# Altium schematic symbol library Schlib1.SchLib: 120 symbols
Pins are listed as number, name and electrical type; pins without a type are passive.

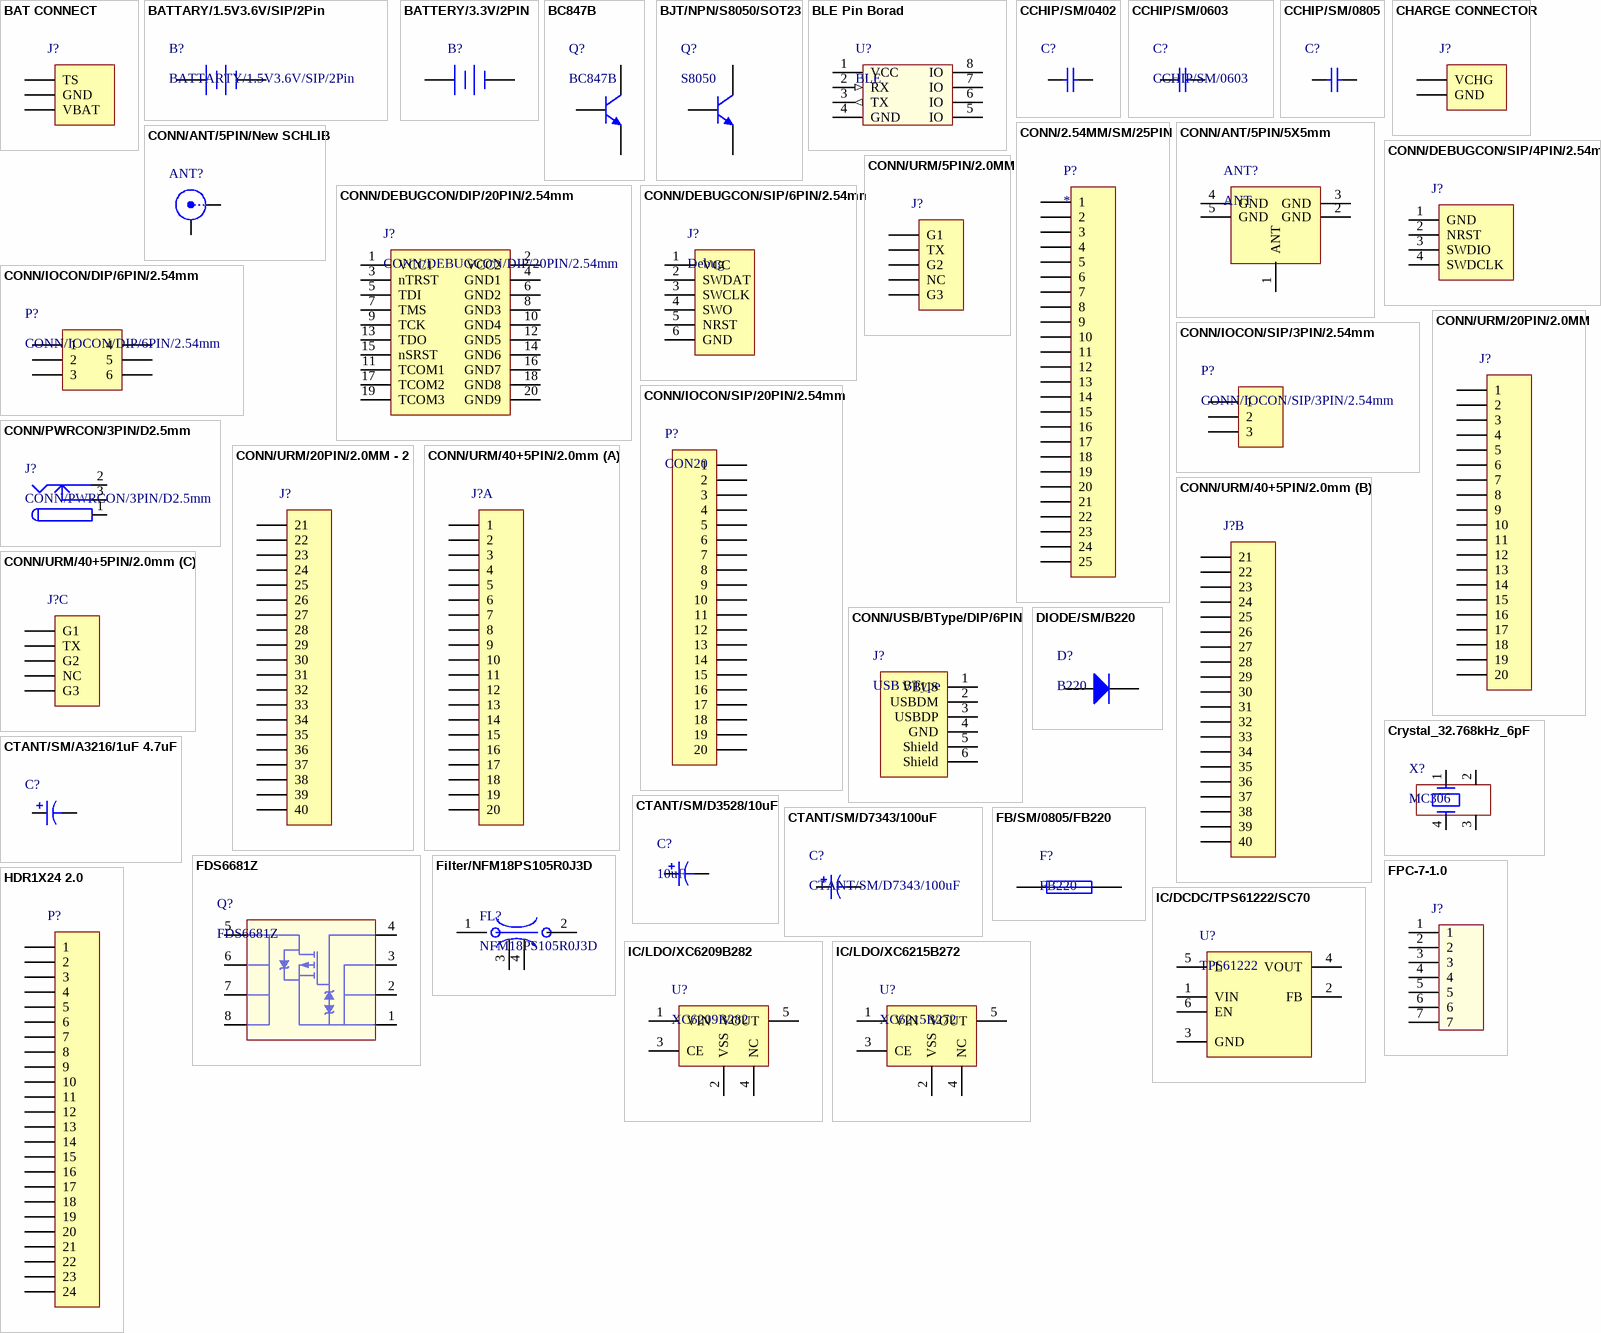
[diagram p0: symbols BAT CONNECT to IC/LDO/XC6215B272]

## BAT CONNECT
designator J?, comment XH-3  (value not drawn)
XH-3 2.0MM 3PIN
footprint XH-3
pins: 1 TS, 2 GND, 3 VBAT

## BATTARY/1.5V3.6V/SIP/2Pin
designator B?, comment BATTARTY/1.5V3.6V/SIP/2Pin
1.5V/3.6V AA电池座(5号电池)
footprint CONN/BATBOX/1.5V/14500
pins: 1 +, 2 -

## BATTERY/3.3V/2PIN
designator B?  (value not drawn)
3.3V纽扣电池(4节并联)CR2032
footprint BATTERY/3.3V/2PIN
pins: 1 +, 2 -

## BC847B
designator Q?
General purpose NPN Transistor
footprint SOT23_BC847B
pins: 1 B, 2 E, 3 C

## BJT/NPN/S8050/SOT23
designator Q?, comment S8050
NPN小功率三极管
footprint SOT-23-3
pins: 1 B, 2 E, 3 C

## BLE Pin Borad
designator U?, comment BLE
BLE Pin Board USRAT SPI  I2C
footprint BLE Pin Board
pins: 1 VCC (power), 2 RX (in), 3 TX (out), 4 GND (power), 5 IO, 6 IO, 7 IO, 8 IO

## CCHIP/SM/0402
designator C?  (value not drawn)
0402贴片电容
footprint 0402 with no topoverlayer
pins: 1, 2

## CCHIP/SM/0603
designator C?
瓷片电容
footprint 0603c
footprint 0402
footprint 0805C
footprint 0603 with no topoverlay
pins: 1, 2

## CCHIP/SM/0805
designator C?  (value not drawn)
瓷片电容
footprint 0805 with no topoverlay
pins: 1, 2

## CHARGE CONNECTOR
designator J?  (value not drawn)
Charge Connector XH-2 2.0MM
footprint XH-2
pins: 1 VCHG, 2 GND

## CONN/2.54MM/SM/25PIN
designator P?
2.54mm间距 25pin 贴片排针
footprint CONN/25PIN/2.54MM/SM
pins: 1, 2, 3, 4, 5, 6, 7, 8, 9, 10, 11, 12, 13, 14, 15, 16, 17, 18, 19, 20, 21, 22, 23, 24, 25

## CONN/ANT/5PIN/5X5mm
designator ANT?, comment ANT
直插天线接口,5PIN,5X5mm
footprint CONN/ANT/5PIN/5X5mm
pins: 1 ANT, 2 GND, 3 GND, 4 GND, 5 GND

## CONN/ANT/5PIN/New SCHLIB
designator ANT?  (value not drawn)
天线连接器
pins: 1 Signal "RF signal", 2 GND "Ground signal", 3 hidden to GND, 4 hidden to GND, 5 hidden to GND

## CONN/DEBUGCON/DIP/20PIN/2.54mm
designator J?
STM32调试接口双排20pin
footprint CONN/DEBUGCON/20PIN
pins: 1 VCC1, 2 VCC2, 3 nTRST, 4 GND1, 5 TDI, 6 GND2, 7 TMS, 8 GND3, 9 TCK, 10 GND4, 11 TCOM1, 12 GND5, 13 TDO, 14 GND6, 15 nSRST, 16 GND7, 17 TCOM2, 18 GND8, 19 TCOM3, 20 GND9

## CONN/DEBUGCON/SIP/4PIN/2.54mm
designator J?  (value not drawn)
STM32仿真、下载接口，4pin，2.54mm
footprint CONN/DEBUGCON/4PIN/2.54MM
footprint CONN/DEBUG CON/2.54mm/4pin/SMT
footprint CONN/FPC/4PIN/0.5MM
pins: 1 GND, 2 NRST, 3 SWDIO, 4 SWDCLK

## CONN/DEBUGCON/SIP/6PIN/2.54mm
designator J?, comment Debug
STM32仿真、下载接口，6pin，2.54mm
footprint CONN/DEBUGCON/SIP/6PIN/2.54mm
pins: 1 VCC, 2 SWDAT, 3 SWCLK, 4 SWO, 5 NRST, 6 GND

## CONN/IOCON/DIP/6PIN/2.54mm
designator P?
2.54mm双排直插6PIN插针
pins: 1, 2, 3, 4, 5, 6

## CONN/IOCON/SIP/3PIN/2.54mm
designator P?
2.54mm单排3pin插针
footprint CONN/SIP/3PIN/2.54mm
pins: 1, 2, 3

## CONN/IOCON/SIP/20PIN/2.54mm
designator P?, comment CON20
20PIN，2.54mm间距接插件
footprint CONN/IOCON/SIP/20PIN/2.54mm
pins: 1, 2, 3, 4, 5, 6, 7, 8, 9, 10, 11, 12, 13, 14, 15, 16, 17, 18, 19, 20

## CONN/PWRCON/3PIN/D2.5mm
designator J?
2.5mm直径电源接头
pins: 1 (power), 1A (power), 1B (power), 2 (power), 2A (power), 2B (power), 3 (power), 3A (power), 3B (power)

## CONN/URM/5PIN/2.0MM
designator J?  (value not drawn)
URM模块引脚,5PIN,2.0MM
footprint CONN/URM/5PIN/2.0MM
pins: G1, G2, G3, NC, TX

## CONN/URM/20PIN/2.0MM
designator J?  (value not drawn)
URM模块引脚,20PIN,2.0MM
footprint CON/URM/20PIN/2.0MM
pins: 1, 2, 3, 4, 5, 6, 7, 8, 9, 10, 11, 12, 13, 14, 15, 16, 17, 18, 19, 20

## CONN/URM/20PIN/2.0MM - 2
designator J?  (value not drawn)
URM模块引脚,20PIN,2.0MM - 2
footprint CONN/URM/20PIN/2.0MM - 2
pins: 21, 22, 23, 24, 25, 26, 27, 28, 29, 30, 31, 32, 33, 34, 35, 36, 37, 38, 39, 40

## CONN/URM/40+5PIN/2.0mm
designator J?  (value not drawn)
URM模块引脚,带边框
footprint URM CONN with Outline
part A pins: 1, 2, 3, 4, 5, 6, 7, 8, 9, 10, 11, 12, 13, 14, 15, 16, 17, 18, 19, 20
part B pins: 21, 22, 23, 24, 25, 26, 27, 28, 29, 30, 31, 32, 33, 34, 35, 36, 37, 38, 39, 40
part C pins: G1, G2, G3, NC, TX

## CONN/USB/BType/DIP/6PIN
designator J?, comment USB BType
B型USB母头方口
footprint CONN/USB/BType/DIP/6PIN
pins: 1 VBUS, 2 USBDM, 3 USBDP, 4 GND, 5 Shield, 6 Shield

## Crystal_32.768kHz_6pF
designator X?, comment MC306
EPSON 32.768kHz 6pF 20ppm
footprint SM8
pins: 1, 2, 3, 4

## CTANT/SM/A3216/1uF 4.7uF
designator C?  (value not drawn)
A3216型钽电容1uF 16V或4.7uF 10V
footprint A3216
pins: 1, 2

## CTANT/SM/D3528/10uF
designator C?, comment 10uF
D3528贴片钽电容10uF
footprint D3528
pins: 1, 2

## CTANT/SM/D7343/100uF
designator C?
D7343 钽电容
footprint D7343
pins: 1, 2

## DIODE/SM/B220
designator D?, comment B220
B220贴片二极管
footprint DIODE/SM/B220
pins: 1 A, 2 K

## FB/SM/0805/FB220
designator F?, comment FB220
磁珠
footprint 0805C
footprint 2012-L
pins: 1, 2

## FDS6681Z
designator Q?
P Channel MOS Vgs = -4.5V Rds = 6.5mΩ
footprint SO-8
pins: 1 S, 2 S, 3 S, 4 G, 5 D, 6 D, 7 D, 8 D

## Filter/NFM18PS105R0J3D
designator FL?, comment NFM18PS105R0J3D
SURFACE MOUNT EMI FILTERS/MURATA
footprint Filter/Surface Mount EMI Filters
pins: 1, 2, 3, 4

## FPC-7-1.0
designator J?  (value not drawn)
FPC 7pin 1.0mm
footprint FPC-7-1.0
pins: 1, 2, 3, 4, 5, 6, 7

## HDR1X24 2.0
designator P?  (value not drawn)
CONNECTOR 1X24Pin 2.0mm
footprint HDR1X24 2.0mm
pins: 1, 2, 3, 4, 5, 6, 7, 8, 9, 10, 11, 12, 13, 14, 15, 16, 17, 18, 19, 20, 21, 22, 23, 24

## IC/DCDC/TPS61222/SC70
designator U?, comment TPS61222
升压电源IC 0.7 - 5V转5V
footprint SC70
pins: 1 VIN, 2 FB, 3 GND, 4 VOUT, 5 L, 6 EN

## IC/LDO/XC6209B282
designator U?, comment XC6209B282
2.8V 150mA 25uA-Iq LDO
footprint SOT-25
pins: 1 VIN, 2 VSS, 3 CE, 4 NC, 5 VOUT

## IC/LDO/XC6215B272
designator U?, comment XC6215B272
2.7V 150mA 0.8uA-Iq LDO
footprint SOT-25
pins: 1 VIN, 2 VSS, 3 CE, 4 NC, 5 VOUT

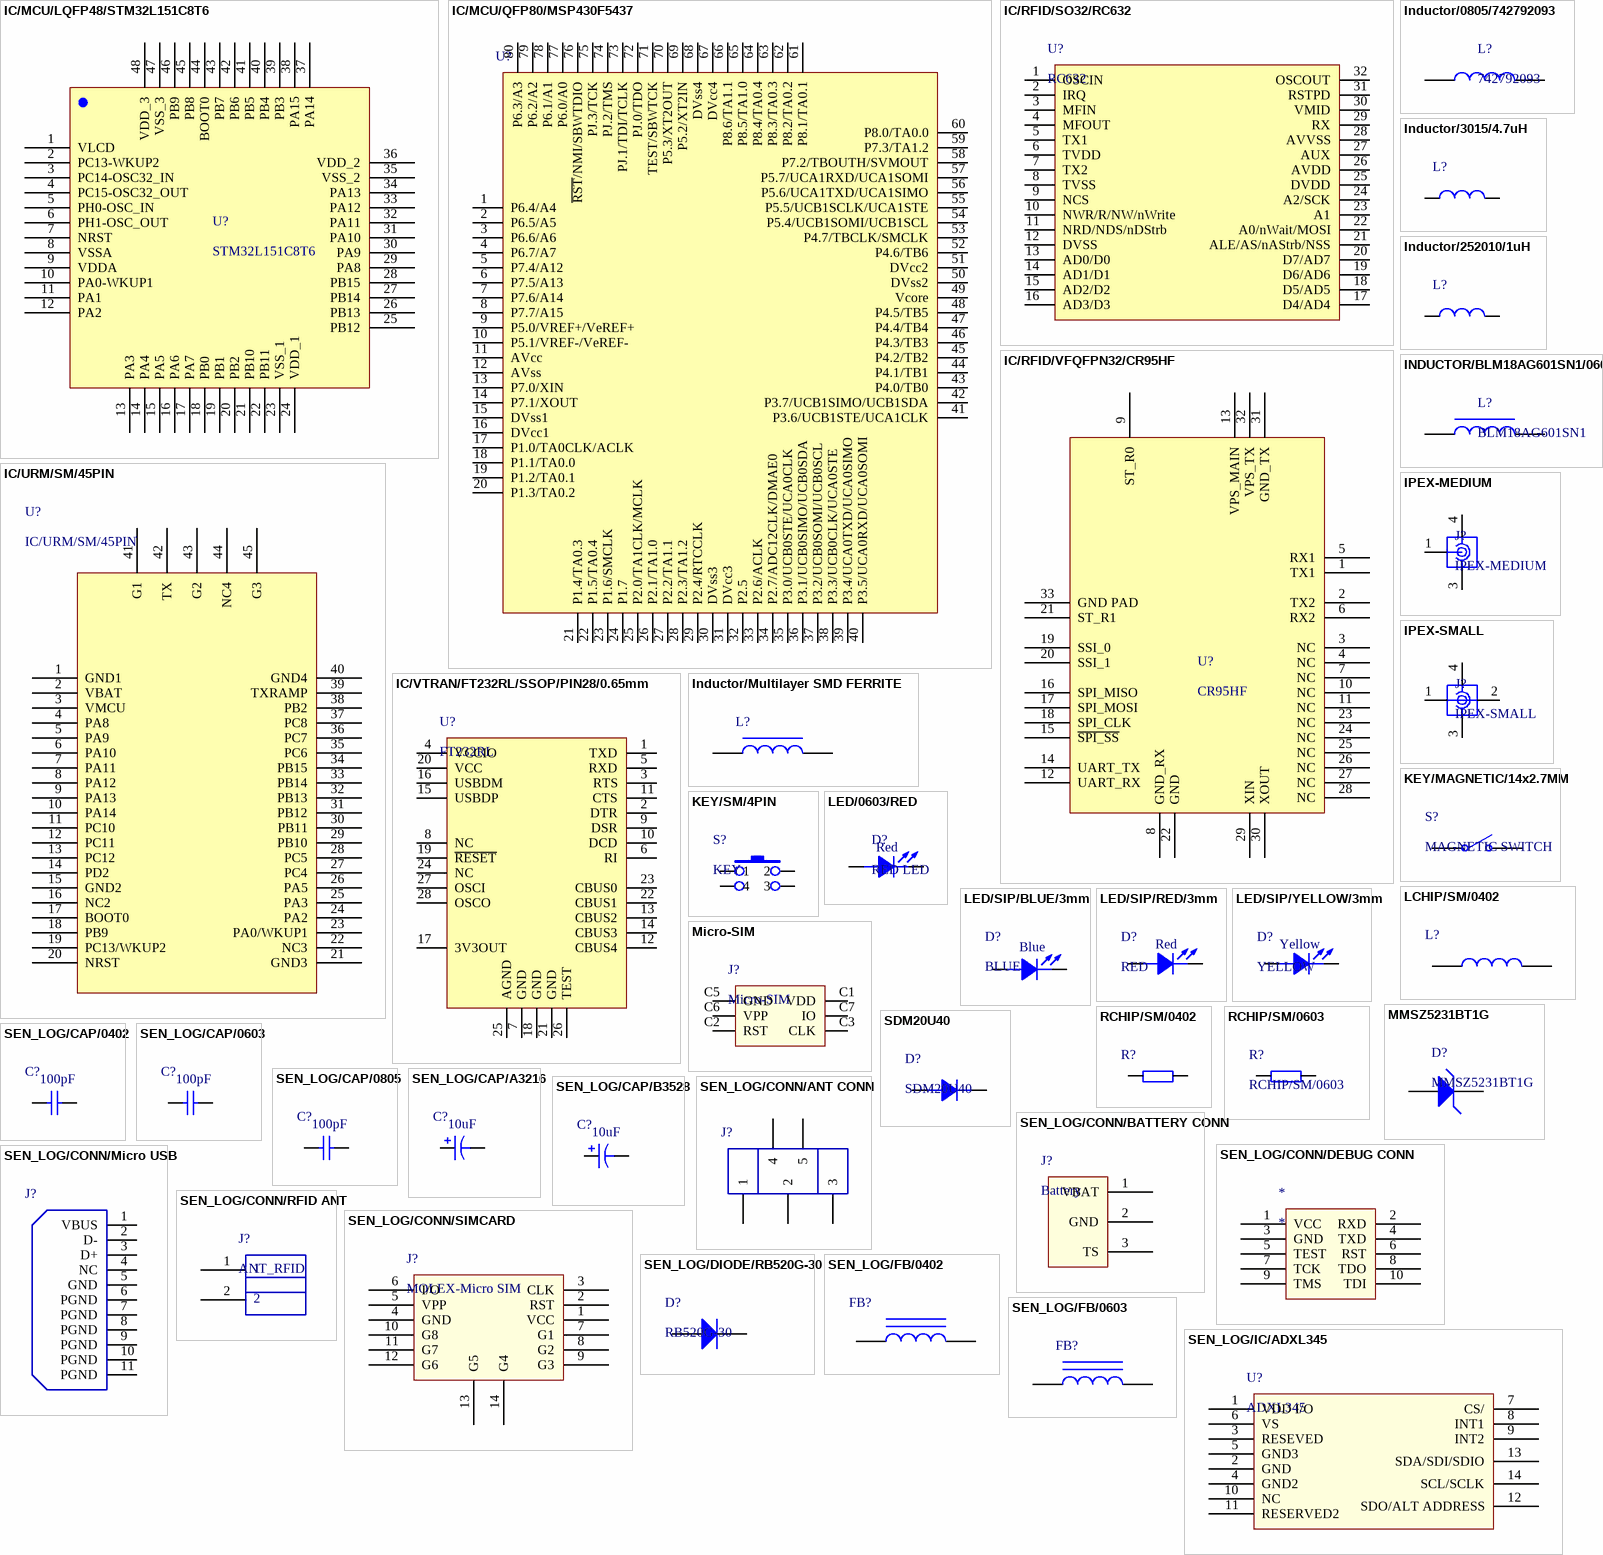
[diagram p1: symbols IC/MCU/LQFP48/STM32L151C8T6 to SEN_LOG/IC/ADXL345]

## IC/MCU/LQFP48/STM32L151C8T6
designator U?, comment STM32L151C8T6
ARM M3 内核低功耗处理器
footprint LQFP48
pins: 1 VLCD, 2 PC13-WKUP2, 3 PC14-OSC32_IN, 4 PC15-OSC32_OUT, 5 PH0-OSC_IN, 6 PH1-OSC_OUT, 7 NRST, 8 VSSA, 9 VDDA, 10 PA0-WKUP1, 11 PA1, 12 PA2, 13 PA3, 14 PA4, 15 PA5, 16 PA6, 17 PA7, 18 PB0, 19 PB1, 20 PB2, 21 PB10, 22 PB11, 23 VSS_1, 24 VDD_1, 25 PB12, 26 PB13, 27 PB14, 28 PB15, 29 PA8, 30 PA9, 31 PA10, 32 PA11, 33 PA12, 34 PA13, 35 VSS_2, 36 VDD_2, 37 PA14, 38 PA15, 39 PB3, 40 PB4, 41 PB5, 42 PB6, 43 PB7, 44 BOOT0, 45 PB8, 46 PB9, 47 VSS_3, 48 VDD_3

## IC/MCU/QFP80/MSP430F5437
designator U?  (value not drawn)
16位低功耗单片机
footprint QFP80/MSP430F5437
pins: 1 P6.4/A4, 2 P6.5/A5, 3 P6.6/A6, 4 P6.7/A7, 5 P7.4/A12, 6 P7.5/A13, 7 P7.6/A14, 8 P7.7/A15, 9 P5.0/VREF+/VeREF+, 10 P5.1/VREF-/VeREF-, 11 AVcc, 12 AVss, 13 P7.0/XIN, 14 P7.1/XOUT, 15 DVss1, 16 DVcc1, 17 P1.0/TA0CLK/ACLK, 18 P1.1/TA0.0, 19 P1.2/TA0.1, 20 P1.3/TA0.2, 21 P1.4/TA0.3, 22 P1.5/TA0.4, 23 P1.6/SMCLK, 24 P1.7, 25 P2.0/TA1CLK/MCLK, 26 P2.1/TA1.0, 27 P2.2/TA1.1, 28 P2.3/TA1.2, 29 P2.4/RTCCLK, 30 DVss3, 31 DVcc3, 32 P2.5, 33 P2.6/ACLK, 34 P2.7/ADC12CLK/DMAE0, 35 P3.0/UCB0STE/UCA0CLK, 36 P3.1/UCB0SIMO/UCB0SDA, 37 P3.2/UCB0SOMI/UCB0SCL, 38 P3.3/UCB0CLK/UCA0STE, 39 P3.4/UCA0TXD/UCA0SIMO, 40 P3.5/UCA0RXD/UCA0SOMI, 41 P3.6/UCB1STE/UCA1CLK, 42 P3.7/UCB1SIMO/UCB1SDA, 43 P4.0/TB0, 44 P4.1/TB1, 45 P4.2/TB2, 46 P4.3/TB3, 47 P4.4/TB4, 48 P4.5/TB5, 49 Vcore, 50 DVss2, 51 DVcc2, 52 P4.6/TB6, 53 P4.7/TBCLK/SMCLK, 54 P5.4/UCB1SOMI/UCB1SCL, 55 P5.5/UCB1SCLK/UCA1STE, 56 P5.6/UCA1TXD/UCA1SIMO, 57 P5.7/UCA1RXD/UCA1SOMI, 58 P7.2/TBOUTH/SVMOUT, 59 P7.3/TA1.2, 60 P8.0/TA0.0, 61 P8.1/TA0.1, 62 P8.2/TA0.2, 63 P8.3/TA0.3, 64 P8.4/TA0.4, 65 P8.5/TA1.0, 66 P8.6/TA1.1, 67 DVcc4, 68 DVss4, 69 P5.2/XT2IN, 70 P5.3/XT2OUT, 71 TEST/SBWTCK, 72 PJ.0/TDO, 73 PJ.1/TDI/TCLK, 74 PJ.2/TMS, 75 PJ.3/TCK, 76 ~{RST}/NMI/SBWTDIO, 77 P6.0/A0, 78 P6.1/A1, 79 P6.2/A2, 80 P6.3/A3

## IC/RFID/SO32/RC632
designator U?, comment RC632
支持14443A、14443B、15693协议的RFID基站芯片
footprint SO32
pins: 1 OSCIN, 2 IRQ, 3 MFIN, 4 MFOUT, 5 TX1, 6 TVDD, 7 TX2, 8 TVSS, 9 NCS, 10 NWR/R/NW/nWrite, 11 NRD/NDS/nDStrb, 12 DVSS, 13 AD0/D0, 14 AD1/D1, 15 AD2/D2, 16 AD3/D3, 17 D4/AD4, 18 D5/AD5, 19 D6/AD6, 20 D7/AD7, 21 ALE/AS/nAStrb/NSS, 22 A0/nWait/MOSI, 23 A1, 24 A2/SCK, 25 DVDD, 26 AVDD, 27 AUX, 28 AVVSS, 29 RX, 30 VMID, 31 RSTPD, 32 OSCOUT

## IC/RFID/VFQFPN32/CR95HF
designator U?, comment CR95HF
RFID读写芯片，支持14443A、B及15693
footprint VFQFPN32 (CR95HF)
pins: 1 TX1, 2 TX2, 3 NC, 4 NC, 5 RX1, 6 RX2, 7 NC, 8 GND_RX, 9 ST_R0, 10 NC, 11 NC, 12 UART_RX, 13 VPS_MAIN, 14 UART_TX, 15 ~{SPI_SS}, 16 SPI_MISO, 17 SPI_MOSI, 18 SPI_CLK, 19 SSI_0, 20 SSI_1, 21 ST_R1, 22 GND, 23 NC, 24 NC, 25 NC, 26 NC, 27 NC, 28 NC, 29 XIN, 30 XOUT, 31 GND_TX, 32 VPS_TX, 33 GND PAD

## IC/URM/SM/45PIN
designator U?
URM模块
footprint IC/URM/45PIN
pins: 1 GND1, 2 VBAT, 3 VMCU, 4 PA8, 5 PA9, 6 PA10, 7 PA11, 8 PA12, 9 PA13, 10 PA14, 11 PC10, 12 PC11, 13 PC12, 14 PD2, 15 GND2, 16 NC2, 17 BOOT0, 18 PB9, 19 PC13/WKUP2, 20 NRST, 21 GND3, 22 NC3, 23 PA0/WKUP1, 24 PA2, 25 PA3, 26 PA5, 27 PC4, 28 PC5, 29 PB10, 30 PB11, 31 PB12, 32 PB13, 33 PB14, 34 PB15, 35 PC6, 36 PC7, 37 PC8, 38 PB2, 39 TXRAMP, 40 GND4, 41 G1, 42 TX, 43 G2, 44 NC4, 45 G3

## IC/VTRAN/FT232RL/SSOP/PIN28/0.65mm
designator U?, comment FT232RL
USB转RS232电平转换
footprint SSOP28/0.65mm
pins: 1 TXD, 2 DTR, 3 RTS, 4 VCCIO, 5 RXD, 6 RI, 7 GND, 8 NC, 9 DSR, 10 DCD, 11 CTS, 12 CBUS4, 13 CBUS2, 14 CBUS3, 15 USBDP, 16 USBDM, 17 3V3OUT, 18 GND, 19 ~{RESET}, 20 VCC, 21 GND, 22 CBUS1, 23 CBUS0, 24 NC, 25 AGND, 26 TEST, 27 OSCI, 28 OSCO

## Inductor/0805/742792093
designator L?, comment 742792093
铁氧体磁珠 Wurth Electronics Inc FERRITE BEAD 2200 OHM .20A 0805
footprint INDUCTOR/0805/742792093
pins: 1, 2

## Inductor/3015/4.7uH
designator L?  (value not drawn)
3015电感，4.7uH
footprint Inductor 3015
pins: 1, 2

## Inductor/252010/1uH
designator L?  (value not drawn)
2.5mmX2.0mmX1.0mm,1uH电感
footprint Inductor 252010
pins: 1, 2

## INDUCTOR/BLM18AG601SN1/0603
designator L?, comment BLM18AG601SN1
村田铁氧体磁珠
footprint 0603c
pins: 1, 2

## Inductor/Multilayer SMD FERRITE
designator L?  (value not drawn)
WURTH ELETRONIK productor,多层铁氧体电感，742792042
footprint Inductor/Multilayer SMD FERRITE
pins: 1, 2

## IPEX-MEDIUM
designator J?
IPEX ANT CONNECTOR MEDIUM
footprint IPEX-MEDIUM
pins: 1, 3, 4

## IPEX-SMALL
designator J?
IPEX ANT CONNECTOR
footprint IPEX-SMALL
pins: 1, 2, 3, 4

## KEY/MAGNETIC/14x2.7MM
designator S?, comment MAGNETIC SWITCH
14X2.7mm干簧管
footprint KEY/MAGNETIC/14X2.7MM
pins: 1 COMMON, 2 NO

## KEY/SM/4PIN
designator S?, comment KEY
贴片四脚按键
footprint KEY/SM/4PIN
pins: 1, 2, 3, 4

## LCHIP/SM/0402
designator L?  (value not drawn)
0402贴片电感
footprint 0402 with no topoverlayer
pins: 1, 2

## LED/0603/RED
designator D?, comment RED LED
0603贴片红色LED
footprint LED/0603
pins: 1 ANODE, 2 CATHODE

## LED/SIP/BLUE/3mm
designator D?, comment BLUE
3mm直插蓝色LED
footprint LED/SIP/3mm
pins: 1 ANODE, 2 CATHODE

## LED/SIP/RED/3mm
designator D?, comment RED
3mm红色直插LED
footprint LED/SIP/3mm
pins: 1 ANODE, 2 CATHODE

## LED/SIP/YELLOW/3mm
designator D?, comment YELLOW
3mm直插黄色LED
footprint LED/SIP/3mm
pins: 1 ANODE, 2 CATHODE

## Micro-SIM
designator J?
Molex Micro-SIM Socket 6pin
footprint MICRO-SIM
pins: C1 VDD, C2 RST, C3 CLK, C5 GND, C6 VPP, C7 IO

## MMSZ5231BT1G
designator D?
Zener diodes 5.1V 500mW SOD-123
footprint SOD-123
pins: 1 A, 2 K

## RCHIP/SM/0402
designator R?  (value not drawn)
0402贴片电阻
footprint 0402 with no topoverlayer
pins: 1, 2

## RCHIP/SM/0603
designator R?
贴片0603电阻
footprint 0603R
pins: 1, 2

## SDM20U40
designator D?
Suface Mount Schottky Barrier Diode
footprint SOD-523
pins: 1 ANODE, 2 CATHODE

## SEN_LOG/CAP/0402
designator C?  (value not drawn)
0402贴片电容
footprint SEN_LOG/RES & CAP/0402
pins: 1, 2

## SEN_LOG/CAP/0603
designator C?  (value not drawn)
0603贴片电容
footprint SEN_LOG/RES & CAP/0603
pins: 1, 2

## SEN_LOG/CAP/0805
designator C?  (value not drawn)
0805贴片电容
footprint SEN_LOG/RES & CAP/0805
footprint 1206-C
pins: 1, 2

## SEN_LOG/CAP/A3216
designator C?  (value not drawn)
A3216贴片钽电容
footprint SEN_LOG/CAP/A3216
footprint TAN-A3216
pins: 1, 2

## SEN_LOG/CAP/B3528
designator C?  (value not drawn)
B3528贴片钽电容
footprint SEN_LOG/CAP/B3528
footprint TAN-B3528
pins: 1, 2

## SEN_LOG/CONN/ANT CONN
designator J?  (value not drawn)
GPS、GPRS天线
pins: 1, 2, 3, 4, 5

## SEN_LOG/CONN/BATTERY CONN
designator J?, comment Battery
三脚电池座
footprint SEN_LOG/CONN/BATTERY CONN
pins: 1 VBAT, 2 GND, 3 TS

## SEN_LOG/CONN/DEBUG CONN
designator *
调试座
pins: 1 VCC, 2 RXD, 3 GND, 4 TXD, 5 TEST, 6 RST, 7 TCK, 8 TDO, 9 TMS, 10 TDI

## SEN_LOG/CONN/Micro USB
designator J?  (value not drawn)
Micro USB接口
pins: 1 VBUS, 2 D-, 3 D+, 4 NC, 5 GND, 6 PGND, 7 PGND, 8 PGND, 9 PGND, 10 PGND, 11 PGND

## SEN_LOG/CONN/RFID ANT
designator J?, comment ANT_RFID
RFID天线接口
footprint SEN_LOG/CONN/RFID ANT
pins: 1, 2

## SEN_LOG/CONN/SIMCARD
designator J?, comment MOLEX-Micro SIM
Micro SIM卡座
pins: 1 VCC, 2 RST, 3 CLK, 4 GND, 5 VPP, 6 I/O, 7 G1, 8 G2, 9 G3, 10 G8, 11 G7, 12 G6, 13 G5, 14 G4

## SEN_LOG/DIODE/RB520G-30
designator D?, comment RB520G-30
肖特基二极管
pins: 1 A, 2 K

## SEN_LOG/FB/0402
designator FB?  (value not drawn)
磁珠0402
footprint SEN_LOG/RES & CAP/0402
pins: 1, 2

## SEN_LOG/FB/0603
designator FB?  (value not drawn)
磁珠 0603
footprint SEN_LOG/RES & CAP/0603
pins: 1, 2

## SEN_LOG/IC/ADXL345
designator U?, comment ADXL345
3轴加速度传感器
pins: 1 VDD I/O, 2 GND, 3 RESEVED, 4 GND2, 5 GND3, 6 VS, 7 CS/, 8 INT1, 9 INT2, 10 NC, 11 RESERVED2, 12 SDO/ALT ADDRESS, 13 SDA/SDI/SDIO, 14 SCL/SCLK

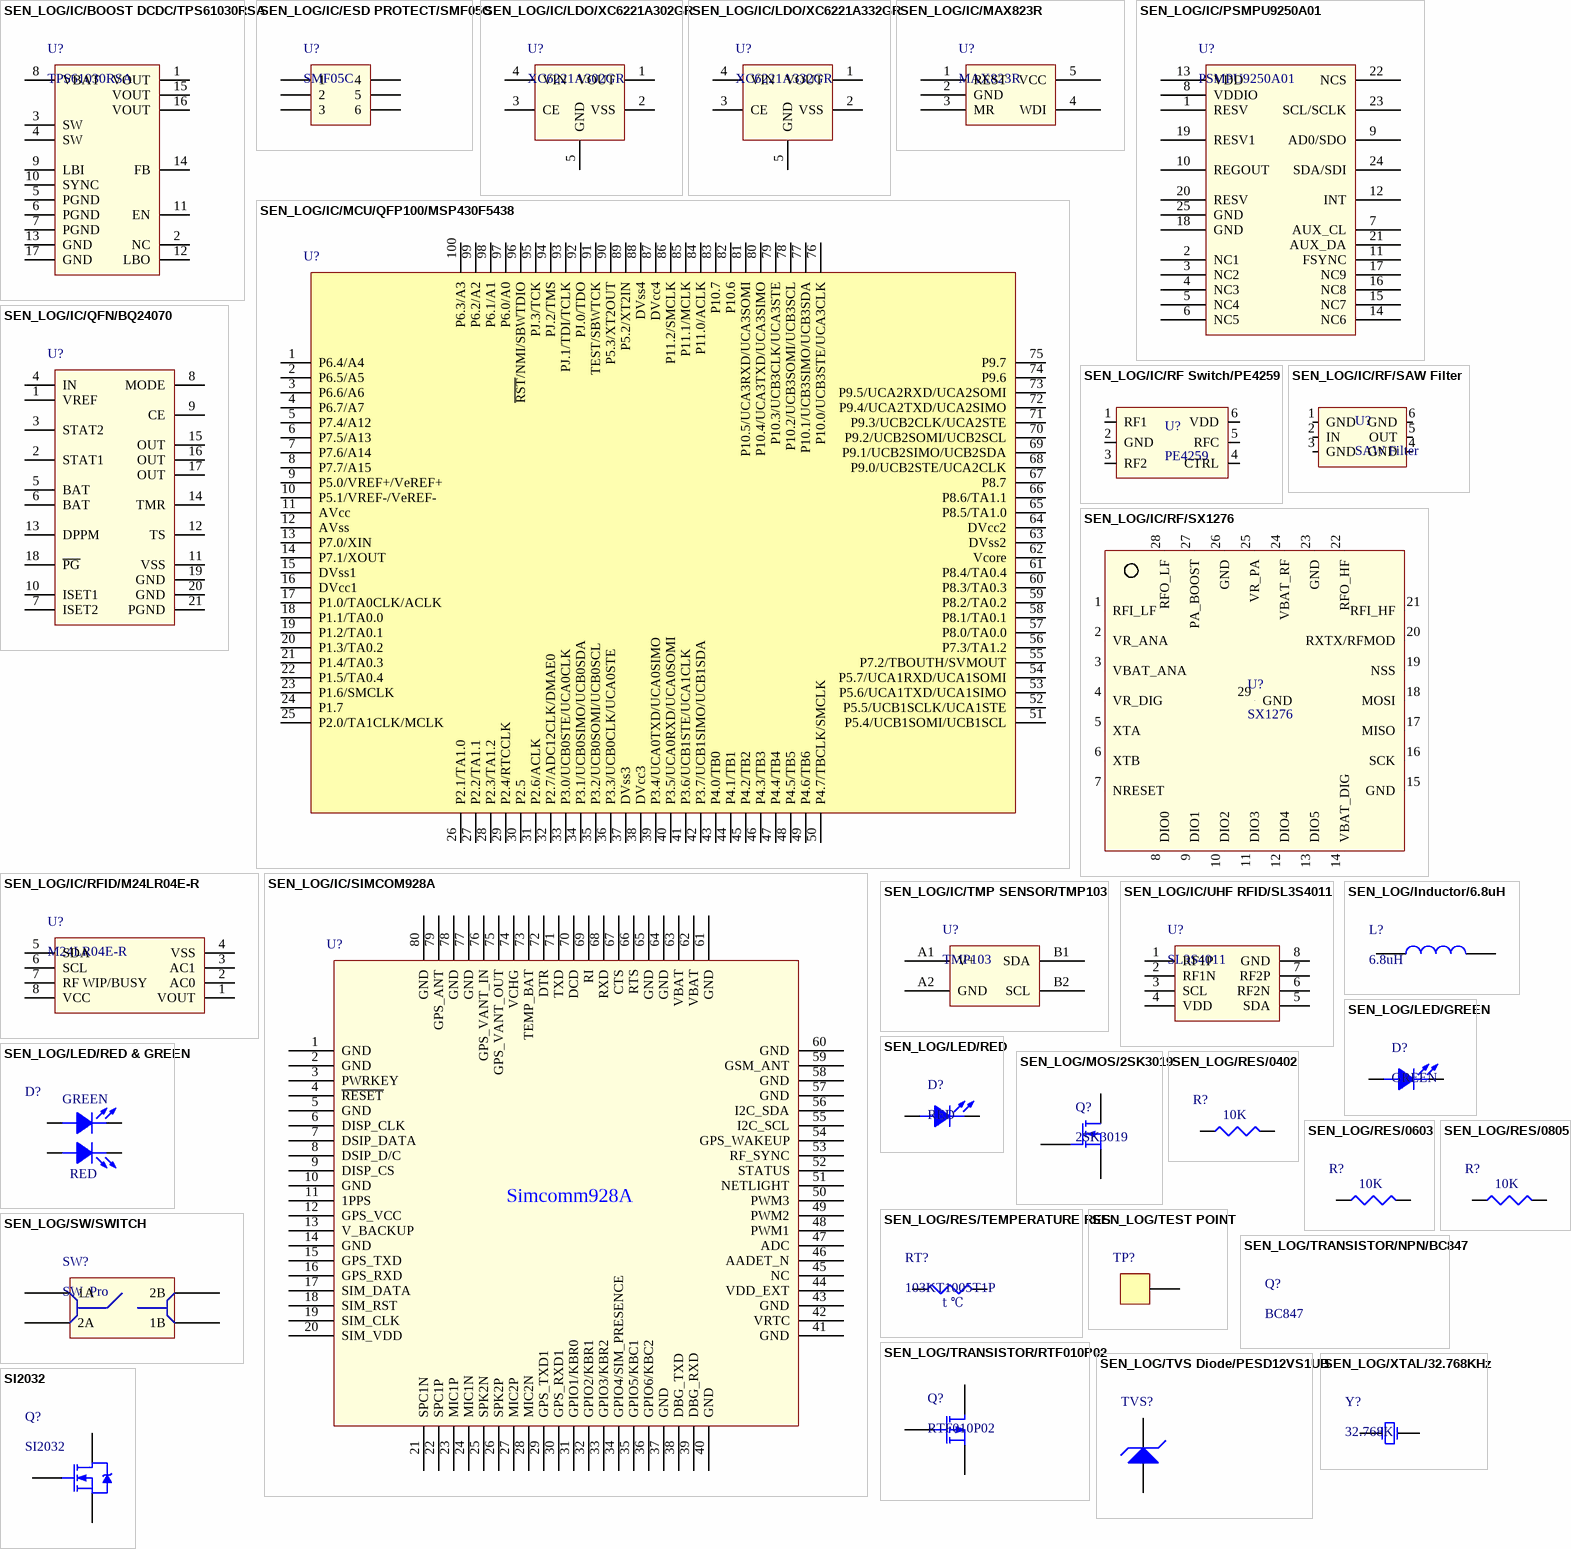
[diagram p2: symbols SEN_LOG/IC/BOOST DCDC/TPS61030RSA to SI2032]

## SEN_LOG/IC/BOOST DCDC/TPS61030RSA
designator U?, comment TPS61030RSA
BOOST升压 DC-DC芯片
footprint SEN_LOG/IC/BOOST DCDC/TPS61030
pins: 1 VOUT, 2 NC, 3 SW, 4 SW, 5 PGND, 6 PGND, 7 PGND, 8 VBAT, 9 LBI, 10 SYNC, 11 EN, 12 LBO, 13 GND, 14 FB, 15 VOUT, 16 VOUT, 17 GND

## SEN_LOG/IC/ESD PROTECT/SMF05C
designator U?, comment SMF05C
ESD保护元件
pins: 1, 2, 3, 4, 5, 6

## SEN_LOG/IC/LDO/XC6221A302GR
designator U?, comment XC6221A302GR
3.0V LDO
pins: 1 VOUT, 2 VSS, 3 CE, 4 VIN, 5 GND

## SEN_LOG/IC/LDO/XC6221A332GR
designator U?, comment XC6221A332GR
3.3V LDO
pins: 1 VOUT, 2 VSS, 3 CE, 4 VIN, 5 GND

## SEN_LOG/IC/MAX823R
designator U?, comment MAX823R
MCU复位及看门狗监控电路
pins: 1 REST, 2 GND, 3 MR, 4 WDI, 5 VCC

## SEN_LOG/IC/MCU/QFP100/MSP430F5438
designator U?  (value not drawn)
16位低功耗单片机 MSP430F5438
footprint QFP100/MSP430F5438
pins: 1 P6.4/A4, 2 P6.5/A5, 3 P6.6/A6, 4 P6.7/A7, 5 P7.4/A12, 6 P7.5/A13, 7 P7.6/A14, 8 P7.7/A15, 9 P5.0/VREF+/VeREF+, 10 P5.1/VREF-/VeREF-, 11 AVcc, 12 AVss, 13 P7.0/XIN, 14 P7.1/XOUT, 15 DVss1, 16 DVcc1, 17 P1.0/TA0CLK/ACLK, 18 P1.1/TA0.0, 19 P1.2/TA0.1, 20 P1.3/TA0.2, 21 P1.4/TA0.3, 22 P1.5/TA0.4, 23 P1.6/SMCLK, 24 P1.7, 25 P2.0/TA1CLK/MCLK, 26 P2.1/TA1.0, 27 P2.2/TA1.1, 28 P2.3/TA1.2, 29 P2.4/RTCCLK, 30 P2.5, 31 P2.6/ACLK, 32 P2.7/ADC12CLK/DMAE0, 33 P3.0/UCB0STE/UCA0CLK, 34 P3.1/UCB0SIMO/UCB0SDA, 35 P3.2/UCB0SOMI/UCB0SCL, 36 P3.3/UCB0CLK/UCA0STE, 37 DVss3, 38 DVcc3, 39 P3.4/UCA0TXD/UCA0SIMO, 40 P3.5/UCA0RXD/UCA0SOMI, 41 P3.6/UCB1STE/UCA1CLK, 42 P3.7/UCB1SIMO/UCB1SDA, 43 P4.0/TB0, 44 P4.1/TB1, 45 P4.2/TB2, 46 P4.3/TB3, 47 P4.4/TB4, 48 P4.5/TB5, 49 P4.6/TB6, 50 P4.7/TBCLK/SMCLK, 51 P5.4/UCB1SOMI/UCB1SCL, 52 P5.5/UCB1SCLK/UCA1STE, 53 P5.6/UCA1TXD/UCA1SIMO, 54 P5.7/UCA1RXD/UCA1SOMI, 55 P7.2/TBOUTH/SVMOUT, 56 P7.3/TA1.2, 57 P8.0/TA0.0, 58 P8.1/TA0.1, 59 P8.2/TA0.2, 60 P8.3/TA0.3, 61 P8.4/TA0.4, 62 Vcore, 63 DVss2, 64 DVcc2, 65 P8.5/TA1.0, 66 P8.6/TA1.1, 67 P8.7, 68 P9.0/UCB2STE/UCA2CLK, 69 P9.1/UCB2SIMO/UCB2SDA, 70 P9.2/UCB2SOMI/UCB2SCL, 71 P9.3/UCB2CLK/UCA2STE, 72 P9.4/UCA2TXD/UCA2SIMO, 73 P9.5/UCA2RXD/UCA2SOMI, 74 P9.6, 75 P9.7, 76 P10.0/UCB3STE/UCA3CLK, 77 P10.1/UCB3SIMO/UCB3SDA, 78 P10.2/UCB3SOMI/UCB3SCL, 79 P10.3/UCB3CLK/UCA3STE, 80 P10.4/UCA3TXD/UCA3SIMO, 81 P10.5/UCA3RXD/UCA3SOMI, 82 P10.6, 83 P10.7, 84 P11.0/ACLK, 85 P11.1/MCLK, 86 P11.2/SMCLK, 87 DVcc4, 88 DVss4, 89 P5.2/XT2IN, 90 P5.3/XT2OUT, 91 TEST/SBWTCK, 92 PJ.0/TDO, 93 PJ.1/TDI/TCLK, 94 PJ.2/TMS, 95 PJ.3/TCK, 96 ~{RST}/NMI/SBWTDIO, 97 P6.0/A0, 98 P6.1/A1, 99 P6.2/A2, 100 P6.3/A3

## SEN_LOG/IC/PSMPU9250A01
designator U?, comment PSMPU9250A01
9轴传感器,加速度计、磁力计、陀螺仪
pins: 1 RESV, 2 NC1, 3 NC2, 4 NC3, 5 NC4, 6 NC5, 7 AUX_CL, 8 VDDIO, 9 AD0/SDO, 10 REGOUT, 11 FSYNC, 12 INT, 13 VDD, 14 NC6, 15 NC7, 16 NC8, 17 NC9, 18 GND, 19 RESV1, 20 RESV, 21 AUX_DA, 22 NCS, 23 SCL/SCLK, 24 SDA/SDI, 25 GND

## SEN_LOG/IC/QFN/BQ24070
designator U?  (value not drawn)
锂电池充电管理芯片
footprint SEN_LOG/IC/BQ24070
pins: 1 VREF, 2 STAT1, 3 STAT2, 4 IN, 5 BAT, 6 BAT, 7 ISET2, 8 MODE, 9 CE, 10 ISET1, 11 VSS, 12 TS, 13 DPPM, 14 TMR, 15 OUT, 16 OUT, 17 OUT, 18 ~{PG}, 19 GND, 20 GND, 21 PGND

## SEN_LOG/IC/RF Switch/PE4259
designator U?, comment PE4259
RF单刀双掷开关
footprint SC70-6 PE4259
pins: 1 RF1, 2 GND, 3 RF2, 4 CTRL, 5 RFC, 6 VDD

## SEN_LOG/IC/RF/SAW Filter
designator U?, comment SAW Filter
声表面滤波器
footprint SAW Filter
pins: 1 GND, 2 IN, 3 GND, 4 GND, 5 OUT, 6 GND

## SEN_LOG/IC/RF/SX1276
designator U?, comment SX1276
Semtech,LoRa双向无线通信芯片
footprint VQFN28
pins: 1 RFI_LF, 2 VR_ANA, 3 VBAT_ANA, 4 VR_DIG, 5 XTA, 6 XTB, 7 NRESET, 8 DIO0, 9 DIO1, 10 DIO2, 11 DIO3, 12 DIO4, 13 DIO5, 14 VBAT_DIG, 15 GND, 16 SCK, 17 MISO, 18 MOSI, 19 NSS, 20 RXTX/RFMOD, 21 RFI_HF, 22 RFO_HF, 23 GND, 24 VBAT_RF, 25 VR_PA, 26 GND, 27 PA_BOOST, 28 RFO_LF, 29 GND

## SEN_LOG/IC/RFID/M24LR04E-R
designator U?, comment M24LR04E-R
双接口I2C存储器
footprint SEN_LOG/IC/RFID/M24LR04E-R
pins: 1 VOUT, 2 AC0, 3 AC1, 4 VSS, 5 SDA, 6 SCL, 7 RF WIP/BUSY, 8 VCC

## SEN_LOG/IC/SIMCOM928A
designator U?  (value not drawn)
GPS/GPRS模块
pins: 1 GND, 2 GND, 3 PWRKEY, 4 ~{RESET}, 5 GND, 6 DISP_CLK, 7 DSIP_DATA, 8 DSIP_D/C, 9 DISP_CS, 10 GND, 11 1PPS, 12 GPS_VCC, 13 V_BACKUP, 14 GND, 15 GPS_TXD, 16 GPS_RXD, 17 SIM_DATA, 18 SIM_RST, 19 SIM_CLK, 20 SIM_VDD, 21 SPC1N, 22 SPC1P, 23 MIC1P, 24 MIC1N, 25 SPK2N, 26 SPK2P, 27 MIC2P, 28 MIC2N, 29 GPS_TXD1, 30 GPS_RXD1, 31 GPIO1/KBR0, 32 GPIO2/KBR1, 33 GPIO3/KBR2, 34 GPIO4/SIM_PRESENCE, 35 GPIO5/KBC1, 36 GPIO6/KBC2, 37 GND, 38 DBG_TXD, 39 DBG_RXD, 40 GND, 41 GND, 42 VRTC, 43 GND, 44 VDD_EXT, 45 NC, 46 AADET_N, 47 ADC, 48 PWM1, 49 PWM2, 50 PWM3, 51 NETLIGHT, 52 STATUS, 53 RF_SYNC, 54 GPS_WAKEUP, 55 I2C_SCL, 56 I2C_SDA, 57 GND, 58 GND, 59 GSM_ANT, 60 GND, 61 GND, 62 VBAT, 63 VBAT, 64 GND, 65 GND, 66 RTS, 67 CTS, 68 RXD, 69 RI, 70 DCD, 71 TXD, 72 DTR, 73 TEMP_BAT, 74 VCHG, 75 GPS_VANT_OUT, 76 GPS_VANT_IN, 77 GND, 78 GND, 79 GPS_ANT, 80 GND

## SEN_LOG/IC/TMP SENSOR/TMP103
designator U?, comment TMP103
温度传感器
pins: A1 V+, A2 GND, B1 SDA, B2 SCL

## SEN_LOG/IC/UHF RFID/SL3S4011
designator U?, comment SL3S4011
UHF频段双接口（I2C）RFID芯片
footprint SEN_LOG/IC/SL3S4011
pins: 1 RF1P, 2 RF1N, 3 SCL, 4 VDD, 5 SDA, 6 RF2N, 7 RF2P, 8 GND

## SEN_LOG/Inductor/6.8uH
designator L?, comment 6.8uH
BOOST芯片所用的电感
footprint SEN_LOG/Inductor/6.8uH
pins: 1, 2

## SEN_LOG/LED/GREEN
designator D?, comment GREEN
蓝色LED灯
pins: 1 ANODE, 2 CATHODE

## SEN_LOG/LED/RED
designator D?, comment RED
红色LED灯
pins: 1 ANODE, 2 CATHODE

## SEN_LOG/LED/RED & GREEN
designator D?  (value not drawn)
红绿双色LED灯
footprint SEN_LOG/LED/RED & GREEN
pins: 1 ANODE, 2 ANODE, 3 CATHODE, 4 CATHODE

## SEN_LOG/MOS/2SK3019
designator Q?, comment 2SK3019
N沟道增强型MOS管
footprint SEN_LOG/MOS/2SK3019
pins: 1 S, 2 G, 3 D

## SEN_LOG/RES/0402
designator R?  (value not drawn)
0402 贴片电阻
footprint SEN_LOG/RES & CAP/0402
pins: 1, 2

## SEN_LOG/RES/0603
designator R?  (value not drawn)
0603贴片电阻
footprint SEN_LOG/RES & CAP/0603
pins: 1, 2

## SEN_LOG/RES/0805
designator R?  (value not drawn)
0805贴片电阻
footprint SEN_LOG/RES & CAP/0805
pins: 1, 2

## SEN_LOG/RES/TEMPERATURE RES
designator RT?, comment 103KT1005T1P
温敏电阻
footprint SEN_LOG/RES & CAP/0402
pins: 1, 2

## SEN_LOG/SW/SWITCH
designator SW?, comment SW_Pro
轻触按键
footprint SEN_LOG/SW/SWITCH
pins: 1A, 1B, 2A, 2B

## SEN_LOG/TEST POINT
designator TP?  (value not drawn)
测试点
footprint SEN_LOG/TEST POINT
pins: 0

## SEN_LOG/TRANSISTOR/NPN/BC847
designator Q?, comment BC847
NPN三极管

## SEN_LOG/TRANSISTOR/RTF010P02
designator Q?, comment RTF010P02
P沟道MOS管
footprint SEN_LOG/TRANSISTOR/RTF010P02
pins: 1 G, 2 S, 3 D

## SEN_LOG/TVS Diode/PESD12VS1UB
designator TVS?  (value not drawn)
ESD保护二极管\浪涌抑制二极管
pins: 1 A, 2 K

## SEN_LOG/XTAL/32.768KHz
designator Y?, comment 32.768K
32.768KHz晶振
pins: 1 OSC1, 2 OSC2

## SI2032
designator Q?
N Channel MOS Vgs = 4.5V Rds = 57mΩ
footprint SOT23_BC847B
pins: 1 G, 2 S, 3 D

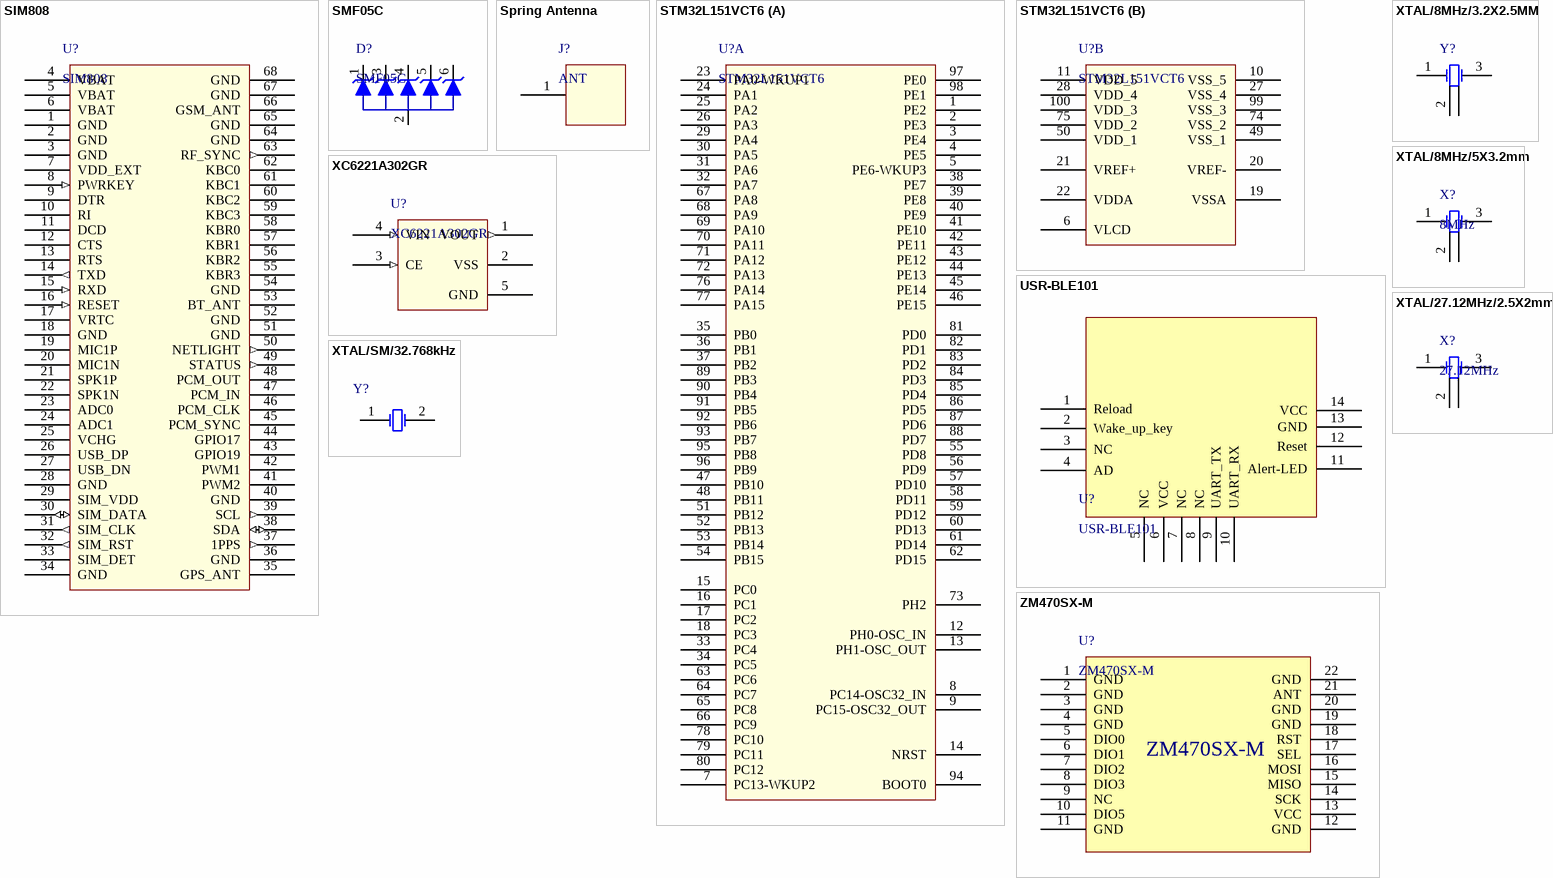
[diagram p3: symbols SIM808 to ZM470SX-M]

## SIM808
designator U?
GPS GPRS Module
footprint SIM808
pins: 1 GND (power), 2 GND (power), 3 GND (power), 4 VBAT (power), 5 VBAT (power), 6 VBAT (power), 7 VDD_EXT (power), 8 PWRKEY (in), 9 DTR (power), 10 RI (power), 11 DCD (power), 12 CTS (power), 13 RTS (power), 14 TXD (out), 15 RXD (in), 16 RESET (in), 17 VRTC (power), 18 GND (power), 19 MIC1P (power), 20 MIC1N (power), 21 SPK1P (power), 22 SPK1N (power), 23 ADC0 (power), 24 ADC1 (power), 25 VCHG (power), 26 USB_DP (power), 27 USB_DN (power), 28 GND (power), 29 SIM_VDD (power), 30 SIM_DATA (io), 31 SIM_CLK (out), 32 SIM_RST (out), 33 SIM_DET, 34 GND (power), 35 GPS_ANT (power), 36 GND (power), 37 1PPS (out), 38 SDA (io), 39 SCL (out), 40 GND (power), 41 PWM2 (power), 42 PWM1 (power), 43 GPIO19 (power), 44 GPIO17 (power), 45 PCM_SYNC (power), 46 PCM_CLK (power), 47 PCM_IN (power), 48 PCM_OUT (power), 49 STATUS (out), 50 NETLIGHT (out), 51 GND (power), 52 GND (power), 53 BT_ANT (power), 54 GND (power), 55 KBR3 (power), 56 KBR2 (power), 57 KBR1 (power), 58 KBR0 (power), 59 KBC3 (power), 60 KBC2 (power), 61 KBC1 (power), 62 KBC0 (power), 63 RF_SYNC (out), 64 GND (power), 65 GND (power), 66 GSM_ANT (power), 67 GND (power), 68 GND (power)

## SMF05C
designator D?
ESD Protect Diode Array 6
footprint SC70-6L_SMF05C
pins: 1 K, 2 A, 3 K, 4 K, 5 K, 6 K

## Spring Antenna
designator J?, comment ANT
Spring ANT
footprint Spring ANT
pins: 1 ANT (power)

## STM32L151VCT6
designator U?
ARM Cortex-M3 MCU LQFP100
footprint TQFP-100
part A pins: 1 PE2, 2 PE3, 3 PE4, 4 PE5, 5 PE6-WKUP3, 7 PC13-WKUP2, 8 PC14-OSC32_IN, 9 PC15-OSC32_OUT, 12 PH0-OSC_IN, 13 PH1-OSC_OUT, 14 NRST, 15 PC0, 16 PC1, 17 PC2, 18 PC3, 23 PA0-WKUP1, 24 PA1, 25 PA2, 26 PA3, 29 PA4, 30 PA5, 31 PA6, 32 PA7, 33 PC4, 34 PC5, 35 PB0, 36 PB1, 37 PB2, 38 PE7, 39 PE8, 40 PE9, 41 PE10, 42 PE11, 43 PE12, 44 PE13, 45 PE14, 46 PE15, 47 PB10, 48 PB11, 51 PB12, 52 PB13, 53 PB14, 54 PB15, 55 PD8, 56 PD9, 57 PD10, 58 PD11, 59 PD12, 60 PD13, 61 PD14, 62 PD15, 63 PC6, 64 PC7, 65 PC8, 66 PC9, 67 PA8, 68 PA9, 69 PA10, 70 PA11, 71 PA12, 72 PA13, 73 PH2, 76 PA14, 77 PA15, 78 PC10, 79 PC11, 80 PC12, 81 PD0, 82 PD1, 83 PD2, 84 PD3, 85 PD4, 86 PD5, 87 PD6, 88 PD7, 89 PB3, 90 PB4, 91 PB5, 92 PB6, 93 PB7, 94 BOOT0, 95 PB8, 96 PB9, 97 PE0, 98 PE1
part B pins: 6 VLCD (power), 10 VSS_5 (power), 11 VDD_5 (power), 19 VSSA (power), 20 VREF- (power), 21 VREF+ (power), 22 VDDA (power), 27 VSS_4 (power), 28 VDD_4 (power), 49 VSS_1 (power), 50 VDD_1 (power), 74 VSS_2 (power), 75 VDD_2 (power), 99 VSS_3 (power), 100 VDD_3 (power)

## USR-BLE101
designator U?
Ultra Small BLE Module 10X10mm
footprint USR-BLE101
pins: 1 Reload, 2 Wake_up_key, 3 NC, 4 AD, 5 NC, 6 VCC, 7 NC, 8 NC, 9 UART_TX, 10 UART_RX, 11 Alert-LED, 12 Reset, 13 GND, 14 VCC

## XC6221A302GR
designator U?
LOW DROUPOUT LDO USP-4 3.0V 120mA
footprint USP-4
pins: 1 VOUT (out), 2 VSS (power), 3 CE (in), 4 VIN (in), 5 GND (power)

## XTAL/8MHz/3.2X2.5MM
designator Y?  (value not drawn)
8MHz无源贴片晶振3.2X2.5MM
footprint XTAL/8MHz/3.2X2.5MM
pins: 1 OSC1, 2 GND, 3 OSC2, 4 NC

## XTAL/8MHz/5X3.2mm
designator X?, comment 8MHz
8MHz无源贴片晶振
footprint XTAL 8MHz 5X3.2mm
pins: 1 OSC1, 2 GND, 3 OSC2, 4 NC

## XTAL/27.12MHz/2.5X2mm
designator X?, comment 27.12MHz
NDK无源贴片晶振
footprint NDK XTAL 27.12MHz 2.5X2MM
pins: 1 OSC1, 2 GND, 3 OSC2, 4 NC

## XTAL/SM/32.768kHz
designator Y?  (value not drawn)
32.768kHz,无源贴片晶振
footprint XTAL 3215 32.768kHz
pins: 1 OSC1, 2 OSC2

## ZM470SX-M
designator U?
470MHz LoRa Transmiter/Receiver
footprint ZM470SX-M
pins: 1 GND, 2 GND, 3 GND, 4 GND, 5 DIO0, 6 DIO1, 7 DIO2, 8 DIO3, 9 NC, 10 DIO5, 11 GND, 12 GND, 13 VCC, 14 SCK, 15 MISO, 16 MOSI, 17 SEL, 18 RST, 19 GND, 20 GND, 21 ANT, 22 GND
